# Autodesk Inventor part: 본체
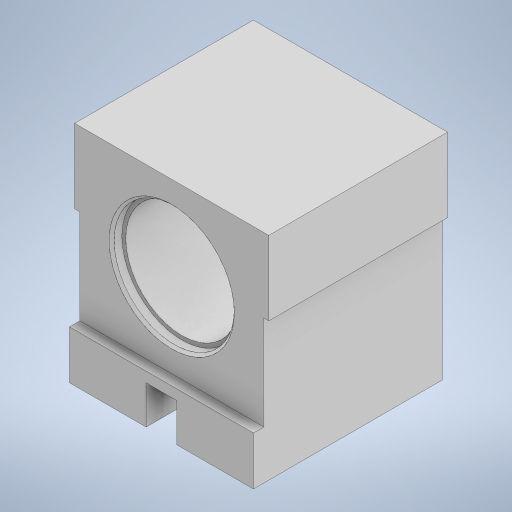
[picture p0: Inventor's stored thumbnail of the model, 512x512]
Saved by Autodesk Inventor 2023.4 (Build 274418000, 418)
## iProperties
Created: 2024-11
Part Number: 본체
Material: 일반
Document SubType Name: Modeling
Designer: EDU
Density: 1 g/cm^3
Appearance: 기본값
Author: EDU
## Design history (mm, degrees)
sketch "스케치1"
  geometry: L1 (-38, 42.5)-(38, 42.5); L2 (38, 42.5)-(38, -42.5); L3 (38, -42.5)-(-38, -42.5); L4 (-38, -42.5)-(-38, 42.5); 3 further points
  constraints: 8 end point, 2 midpoint, 2 parallel, 1 horizontal, 1 horizontal alignment, 1 perpendicular, 1 vertical alignment
  dimensions: "d0" = 76 distance between parallel lines of L2 L4; "d1" = 85 distance between parallel lines of L3 L1
extrude "돌출1" new body sketch "스케치1" distance "d2" = 74; taper "d3" = 0 deg
sketch "스케치2"
  geometry: L1 (-38, -42.5)-(38, -42.5) reference; L2 (38, -42.5)-(38, 42.5) reference; L3 (38, 42.5)-(-38, 42.5) reference; L4 (-38, 42.5)-(-38, -42.5) reference; L5 (-38, -42.5)-(38, -42.5) reference; L6 (-6, -42.5)-(-6, -27.5); L7 (-6, -27.5)-(6, -27.5); L8 (6, -27.5)-(6, -42.5); 4 further points
  constraints: 6 end point, 2 perpendicular, 2 point on line, 1 midpoint, 1 vertical, 1 vertical alignment
  dimensions: "d4" = 15 distance between parallel lines of L1 L7; "d5" = 12 distance between parallel lines of L8 L6
extrude "돌출2" cut sketch "스케치2" stored distance "d6" = 74; taper "d7" = 0 deg
sketch "스케치3"
  geometry: L1 (0, 85)-(0, 0) reference; L2 (0, 0)-(74, 0) reference; L3 (74, 85)-(74, 0) reference; L4 (0, 85)-(74, 85) reference; L5 (0, 85)-(74, 85) reference; L6 (70, 85)-(70, 19); L7 (70, 19)-(74, 19); L8 (74, 0)-(74, 85) reference; 3 further points
  constraints: 4 end point, 2 point on line, 1 perpendicular, 1 vertical
  dimensions: "d8" = 66 distance between parallel lines of L7 L4; "d9" = 4 distance between parallel lines of L3 L6
extrude "돌출3" cut sketch "스케치3" stored distance "d10" = 10; taper "d11" = 0 deg
sketch "스케치4"
  geometry: L1 (38, -23.5)-(-38, -23.5) reference; L2 (-38, -23.5)-(-38, -42.5) reference; L3 (-38, -42.5)-(-6, -42.5) reference; L4 (-6, -42.5)-(-6, -27.5) reference; L5 (-6, -27.5)-(6, -27.5) reference; L6 (6, -27.5)-(6, -42.5) reference; L7 (6, -42.5)-(38, -42.5) reference; L8 (38, -42.5)-(38, -23.5) reference; L9 (6, -42.5)-(38, -42.5) reference; L10 (36, -42.5)-(36, 13.5); L11 (36, 13.5)-(38, 13.5); L12 (-38, -42.5)-(-6, -42.5) reference; L13 (-36, -42.5)-(-36, 13.5); L14 (-36, 13.5)-(-38, 13.5); L15 (38, 42.5)-(38, -23.5) reference; L16 (-38, 42.5)-(38, 42.5) reference; L17 (-38, -23.5)-(-38, 42.5) reference; L18 (-38, -23.5)-(38, -23.5) reference; 7 further points
  constraints: 8 end point, 3 perpendicular, 2 point on line, 1 vertical
  dimensions: "d12" = 56 distance between parallel lines of L7 L11; "d13" = 56 distance between parallel lines of L3 L14; "d14" = 2 distance between parallel lines of L13 L2; "d15" = 2 distance between parallel lines of L10 L8
extrude "돌출4" cut sketch "스케치4" stored distance "d16" = 10; taper "d17" = 0 deg
sketch "스케치5"
  geometry: L1 (74, -66)-(74, -29) reference; L2 (74, -29)-(76, -29) reference; L3 (76, 0)-(76, -29) reference; L4 (0, 0)-(76, 0) reference; L5 (0, -29)-(0, 0) reference; L6 (0, -29)-(2, -29) reference; L7 (2, -29)-(2, -66) reference; L8 (2, -66)-(74, -66) reference; C1 r 23.5 at (38, -33); 1 further point
  constraints: 1 centre point
  dimensions: "d18" = 47 diameter of C1; "d19" = 33 distance from line of C1.centre L4
extrude "돌출5" cut sketch "스케치5" distance "d20" = 4; taper "d21" = 0 deg
sketch "스케치6"
  geometry: C1 r 23.5 at (0, 9.5) reference; C2 r 22 at (0, 9.5); 1 further point
  constraints: 1 centre point, 1 coincident
  dimensions: "d22" = 44 diameter of C2
extrude "돌출6" cut sketch "스케치6" distance "d23" = 56; taper "d24" = 0 deg
sketch "스케치7"
  geometry: C1 r 22 at (0, 0) reference; C2 r 17.5 at (0, 0); 1 further point
  constraints: 1 centre point, 1 coincident
  dimensions: "d25" = 35 diameter of C2
extrude "돌출7" cut sketch "스케치7" distance "d26" = 11; taper "d27" = 0 deg
sketch "스케치8"
  geometry: C1 r 17.5 at (0, 0) reference; C2 r 15 at (0, 0); 1 further point
  constraints: 1 centre point, 1 coincident
  dimensions: "d28" = 30 diameter of C2
extrude "돌출8" cut sketch "스케치8" distance "d29" = 3; taper "d30" = 0 deg
fillet "모깎기1" dims "d31" = 3
fillet "모깎기2" dims "d32" = 0.6
chamfer "모따기1" distance "d33" = 1; stored, may be unused: second distance "d34" = 2, angle "d35" = 45 deg
fillet "모깎기3" dims "d36" = 3
chamfer "모따기2" distance "d37" = 1; stored, may be unused: second distance "d38" = 2, angle "d39" = 45 deg
node "솔리드1"
node "투영된 루프1"
node "투영된 루프2"
node "투영된 루프3"
node "투영된 루프4"
node "투영된 루프5"
node "투영된 루프6"
node "투영된 루프7"
node "투영된 루프8"
